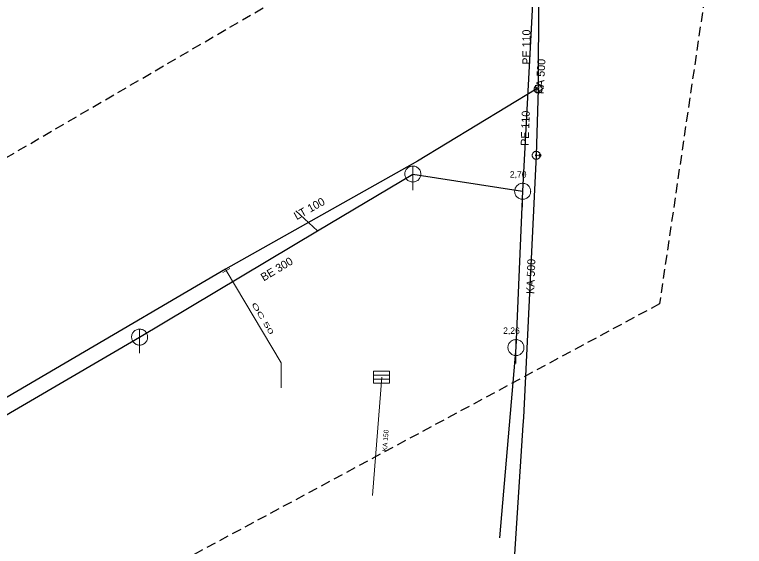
# Model space of a CAD drawing. Extents: x -689189 to -688666, y -973229 to -972850.
# Drawn here: x -688858.3 to -688767.2, y -972988.4 to -972922 of the extents above; entities that cross this region are included whole.
import ezdxf

# ---------------------------------------------------------------- set-up
doc = ezdxf.new("R2010")
doc.units = 0
doc.header["$LTSCALE"] = 0.4
doc.linetypes.add('MEDIUM_DASHED', pattern=[4.5, 3, -1.5])
doc.layers.add('1', color=7, linetype='Continuous')
for name, color, linetype, lineweight in [('11', 7, 'Continuous', 13), ('13', 7, 'Continuous', 13), ('14', 7, 'Continuous', 13), ('17', 7, 'Continuous', 25), ('22', 7, 'Continuous', 13), ('34', 7, 'Continuous', 13), ('47', 7, 'Continuous', 13), ('63', 7, 'MEDIUM_DASHED', 25), ('9', 7, 'Continuous', 13)]:
    doc.layers.add(name, color=color, linetype=linetype, lineweight=lineweight)

msp = doc.modelspace()

# ---------------------------------------------------------------- linework, layer by layer
at = {"layer": '11'}
for p, q in [((-688823.171, -972946.507), (-688820.467, -972949.003)), ((-688812.451, -972967.272), (-688813.601, -972982.025))]:
    msp.add_line(p, q, dxfattribs=at)
at = {"layer": '13'}
msp.add_lwpolyline([(-688831.857, -972953.962), (-688825.015, -972965.466), (-688825.015, -972968.601)], dxfattribs=at)
at = {"layer": '14', "lineweight": 25}
for p, q in [((-688793.27, -972913.607), (-688794.848, -972944.059)), ((-688808.566, -972941.901), (-688794.848, -972944.059)), ((-688794.848, -972944.059), (-688795.686, -972963.568)), ((-688795.686, -972963.568), (-688797.745, -972987.344))]:
    msp.add_line(p, q, dxfattribs=at)
at = {"layer": '14'}
for p, q in [((-688792.916, -972931.292), (-688793.177, -972931.292)), ((-688792.916, -972931.292), (-688792.912, -972931.053)), ((-688793.154, -972939.566), (-688792.683, -972939.579)), ((-688831.953, -972953.798), (-688831.857, -972953.962))]:
    msp.add_line(p, q, dxfattribs=at)
at = {"layer": '14', "lineweight": 25}
for points in [[(-688842.688, -972962.265), (-688820.467, -972949.003), (-688808.566, -972941.901)], [(-688951.66, -973026.25), (-688926.154, -973011.013), (-688911.58, -973002.657), (-688886.468, -972987.81), (-688879.879, -972983.977), (-688842.688, -972962.265)]]:
    msp.add_lwpolyline(points, dxfattribs=at)
at = {"layer": '17'}
for p, q in [((-688792.866, -972919.454), (-688792.912, -972931.053)), ((-688792.916, -972931.292), (-688793.154, -972939.566))]:
    msp.add_line(p, q, dxfattribs=at)
for points in [[(-688793.177, -972931.292), (-688807.995, -972940.316), (-688831.953, -972953.798), (-688872.059, -972977.27), (-688873.897, -972978.38), (-688874.46, -972978.719), (-688897.906, -972992.515), (-688964.11, -973031.504), (-688973.449, -973037.003), (-688975.824, -973038.94)], [(-688793.154, -972939.566), (-688794.76, -972972.294), (-688794.823, -972973.274), (-688797.579, -973015.741)]]:
    msp.add_lwpolyline(points, dxfattribs=at)
at = {"layer": '22'}
for p, q in [((-688808.566, -972943.901), (-688808.565, -972940.901)), ((-688794.848, -972946.059), (-688794.847, -972943.059)), ((-688842.688, -972964.265), (-688842.687, -972961.265)), ((-688795.686, -972965.568), (-688795.685, -972962.568)), ((-688813.462, -972967.015), (-688811.462, -972967.015)), ((-688813.462, -972967.515), (-688811.462, -972967.515))]:
    msp.add_line(p, q, dxfattribs=at)
for points in [[(-688807.566, -972941.901), (-688807.571, -972941.792), (-688807.589, -972941.684), (-688807.619, -972941.578), (-688807.659, -972941.477), (-688807.711, -972941.38), (-688807.773, -972941.29), (-688807.845, -972941.207), (-688807.925, -972941.133), (-688808.013, -972941.067), (-688808.107, -972941.012), (-688808.207, -972940.967), (-688808.312, -972940.934), (-688808.419, -972940.912), (-688808.528, -972940.902), (-688808.638, -972940.904), (-688808.746, -972940.918), (-688808.853, -972940.943), (-688808.956, -972940.98), (-688809.054, -972941.029), (-688809.146, -972941.087), (-688809.232, -972941.156), (-688809.309, -972941.233), (-688809.378, -972941.319), (-688809.437, -972941.411), (-688809.485, -972941.509), (-688809.522, -972941.612), (-688809.548, -972941.719), (-688809.562, -972941.827), (-688809.565, -972941.937), (-688809.555, -972942.046), (-688809.534, -972942.153), (-688809.5, -972942.257), (-688809.456, -972942.357), (-688809.401, -972942.452), (-688809.335, -972942.54), (-688809.261, -972942.62), (-688809.178, -972942.692), (-688809.088, -972942.754), (-688808.992, -972942.806), (-688808.89, -972942.847), (-688808.785, -972942.877), (-688808.677, -972942.895), (-688808.567, -972942.901), (-688808.458, -972942.895), (-688808.35, -972942.877), (-688808.245, -972942.848), (-688808.143, -972942.807), (-688808.046, -972942.755), (-688807.956, -972942.693), (-688807.873, -972942.622), (-688807.798, -972942.542), (-688807.733, -972942.454), (-688807.677, -972942.36), (-688807.633, -972942.26), (-688807.599, -972942.156), (-688807.577, -972942.048), (-688807.567, -972941.939)], [(-688793.848, -972944.059), (-688793.853, -972943.95), (-688793.871, -972943.842), (-688793.901, -972943.736), (-688793.941, -972943.635), (-688793.993, -972943.538), (-688794.055, -972943.448), (-688794.127, -972943.365), (-688794.207, -972943.291), (-688794.295, -972943.225), (-688794.389, -972943.17), (-688794.489, -972943.125), (-688794.594, -972943.092), (-688794.701, -972943.07), (-688794.81, -972943.06), (-688794.92, -972943.062), (-688795.028, -972943.076), (-688795.135, -972943.101), (-688795.238, -972943.138), (-688795.336, -972943.187), (-688795.428, -972943.245), (-688795.514, -972943.314), (-688795.591, -972943.391), (-688795.66, -972943.477), (-688795.719, -972943.569), (-688795.767, -972943.667), (-688795.804, -972943.77), (-688795.83, -972943.877), (-688795.844, -972943.985), (-688795.847, -972944.095), (-688795.837, -972944.204), (-688795.816, -972944.311), (-688795.782, -972944.415), (-688795.738, -972944.515), (-688795.683, -972944.61), (-688795.617, -972944.698), (-688795.543, -972944.778), (-688795.46, -972944.85), (-688795.37, -972944.912), (-688795.274, -972944.964), (-688795.172, -972945.005), (-688795.067, -972945.035), (-688794.959, -972945.053), (-688794.849, -972945.059), (-688794.74, -972945.053), (-688794.632, -972945.035), (-688794.527, -972945.006), (-688794.425, -972944.965), (-688794.328, -972944.913), (-688794.238, -972944.851), (-688794.155, -972944.78), (-688794.08, -972944.7), (-688794.015, -972944.612), (-688793.959, -972944.518), (-688793.915, -972944.418), (-688793.881, -972944.314), (-688793.859, -972944.206), (-688793.849, -972944.097)], [(-688841.688, -972962.265), (-688841.693, -972962.156), (-688841.711, -972962.048), (-688841.741, -972961.942), (-688841.781, -972961.841), (-688841.833, -972961.744), (-688841.895, -972961.654), (-688841.967, -972961.571), (-688842.047, -972961.497), (-688842.135, -972961.431), (-688842.229, -972961.376), (-688842.329, -972961.331), (-688842.434, -972961.298), (-688842.541, -972961.276), (-688842.65, -972961.266), (-688842.76, -972961.268), (-688842.868, -972961.282), (-688842.975, -972961.307), (-688843.078, -972961.344), (-688843.176, -972961.393), (-688843.268, -972961.451), (-688843.354, -972961.52), (-688843.431, -972961.597), (-688843.5, -972961.683), (-688843.559, -972961.775), (-688843.607, -972961.873), (-688843.644, -972961.976), (-688843.67, -972962.083), (-688843.684, -972962.191), (-688843.687, -972962.301), (-688843.677, -972962.41), (-688843.656, -972962.517), (-688843.622, -972962.621), (-688843.578, -972962.721), (-688843.523, -972962.816), (-688843.457, -972962.904), (-688843.383, -972962.984), (-688843.3, -972963.056), (-688843.21, -972963.118), (-688843.114, -972963.17), (-688843.012, -972963.211), (-688842.907, -972963.241), (-688842.799, -972963.259), (-688842.689, -972963.265), (-688842.58, -972963.259), (-688842.472, -972963.241), (-688842.367, -972963.212), (-688842.265, -972963.171), (-688842.168, -972963.119), (-688842.078, -972963.057), (-688841.995, -972962.986), (-688841.92, -972962.906), (-688841.855, -972962.818), (-688841.799, -972962.724), (-688841.755, -972962.624), (-688841.721, -972962.52), (-688841.699, -972962.412), (-688841.689, -972962.303)], [(-688794.686, -972963.568), (-688794.691, -972963.459), (-688794.709, -972963.351), (-688794.739, -972963.245), (-688794.779, -972963.144), (-688794.831, -972963.047), (-688794.893, -972962.957), (-688794.965, -972962.874), (-688795.045, -972962.8), (-688795.133, -972962.734), (-688795.227, -972962.679), (-688795.327, -972962.634), (-688795.432, -972962.601), (-688795.539, -972962.579), (-688795.648, -972962.569), (-688795.758, -972962.571), (-688795.866, -972962.585), (-688795.973, -972962.61), (-688796.076, -972962.647), (-688796.174, -972962.696), (-688796.266, -972962.754), (-688796.352, -972962.823), (-688796.429, -972962.9), (-688796.498, -972962.986), (-688796.557, -972963.078), (-688796.605, -972963.176), (-688796.642, -972963.279), (-688796.668, -972963.386), (-688796.682, -972963.494), (-688796.685, -972963.604), (-688796.675, -972963.713), (-688796.654, -972963.82), (-688796.62, -972963.924), (-688796.576, -972964.024), (-688796.521, -972964.119), (-688796.455, -972964.207), (-688796.381, -972964.287), (-688796.298, -972964.359), (-688796.208, -972964.421), (-688796.112, -972964.473), (-688796.01, -972964.514), (-688795.905, -972964.544), (-688795.797, -972964.562), (-688795.687, -972964.568), (-688795.578, -972964.562), (-688795.47, -972964.544), (-688795.365, -972964.515), (-688795.263, -972964.474), (-688795.166, -972964.422), (-688795.076, -972964.36), (-688794.993, -972964.289), (-688794.918, -972964.209), (-688794.853, -972964.121), (-688794.797, -972964.027), (-688794.753, -972963.927), (-688794.719, -972963.823), (-688794.697, -972963.715), (-688794.687, -972963.606)], [(-688813.462, -972966.515), (-688811.462, -972966.515), (-688811.462, -972968.015), (-688813.462, -972968.015)]]:
    msp.add_lwpolyline(points, close=True, dxfattribs=at)
at = {"layer": '34'}
for p, q in [((-688793.245, -972930.796), (-688793.109, -972931.787)), ((-688792.412, -972931.026), (-688793.411, -972931.078)), ((-688831.425, -972953.709), (-688832.289, -972954.213))]:
    msp.add_line(p, q, dxfattribs=at)
at = {"layer": '47'}
for points in [[(-688792.51, -972930.999), (-688792.543, -972930.958), (-688792.58, -972930.921), (-688792.621, -972930.889), (-688792.664, -972930.859), (-688792.711, -972930.835), (-688792.76, -972930.817), (-688792.81, -972930.804), (-688792.862, -972930.795), (-688792.914, -972930.792), (-688792.966, -972930.794), (-688793.019, -972930.802), (-688793.069, -972930.816), (-688793.118, -972930.834), (-688793.164, -972930.858), (-688793.208, -972930.886), (-688793.249, -972930.919), (-688793.286, -972930.956), (-688793.319, -972930.997), (-688793.348, -972931.04), (-688793.372, -972931.087), (-688793.39, -972931.136), (-688793.404, -972931.187), (-688793.413, -972931.239), (-688793.416, -972931.29), (-688793.413, -972931.342), (-688793.405, -972931.395), (-688793.392, -972931.445), (-688793.373, -972931.494), (-688793.349, -972931.54), (-688793.321, -972931.584), (-688793.288, -972931.625), (-688793.251, -972931.662), (-688793.211, -972931.696), (-688793.167, -972931.724), (-688793.12, -972931.748), (-688793.072, -972931.767), (-688793.021, -972931.781), (-688792.969, -972931.789), (-688792.917, -972931.792), (-688792.865, -972931.789), (-688792.812, -972931.781), (-688792.762, -972931.768), (-688792.713, -972931.749), (-688792.667, -972931.725), (-688792.623, -972931.697), (-688792.582, -972931.664), (-688792.545, -972931.627), (-688792.512, -972931.587), (-688792.483, -972931.543), (-688792.459, -972931.496), (-688792.44, -972931.448), (-688792.427, -972931.397), (-688792.419, -972931.346), (-688792.416, -972931.293), (-688792.418, -972931.241), (-688792.426, -972931.188), (-688792.44, -972931.139), (-688792.458, -972931.089), (-688792.482, -972931.043)], [(-688792.849, -972931.243), (-688792.854, -972931.236), (-688792.861, -972931.231), (-688792.867, -972931.226), (-688792.874, -972931.221), (-688792.882, -972931.217), (-688792.89, -972931.214), (-688792.898, -972931.211), (-688792.907, -972931.21), (-688792.915, -972931.21), (-688792.924, -972931.21), (-688792.933, -972931.211), (-688792.941, -972931.214), (-688792.949, -972931.217), (-688792.956, -972931.22), (-688792.964, -972931.225), (-688792.971, -972931.23), (-688792.976, -972931.237), (-688792.981, -972931.243), (-688792.986, -972931.25), (-688792.99, -972931.258), (-688792.993, -972931.266), (-688792.996, -972931.274), (-688792.997, -972931.283), (-688792.998, -972931.292), (-688792.997, -972931.3), (-688792.996, -972931.309), (-688792.993, -972931.317), (-688792.99, -972931.325), (-688792.987, -972931.332), (-688792.982, -972931.34), (-688792.977, -972931.347), (-688792.97, -972931.352), (-688792.964, -972931.357), (-688792.957, -972931.362), (-688792.949, -972931.366), (-688792.942, -972931.37), (-688792.933, -972931.372), (-688792.924, -972931.373), (-688792.915, -972931.374), (-688792.907, -972931.373), (-688792.898, -972931.372), (-688792.89, -972931.369), (-688792.882, -972931.366), (-688792.875, -972931.363), (-688792.867, -972931.358), (-688792.86, -972931.353), (-688792.855, -972931.346), (-688792.85, -972931.34), (-688792.845, -972931.333), (-688792.841, -972931.325), (-688792.837, -972931.318), (-688792.835, -972931.309), (-688792.834, -972931.3), (-688792.834, -972931.292), (-688792.834, -972931.283), (-688792.835, -972931.274), (-688792.838, -972931.266), (-688792.841, -972931.258), (-688792.844, -972931.251)], [(-688792.748, -972939.273), (-688792.781, -972939.232), (-688792.818, -972939.195), (-688792.859, -972939.163), (-688792.902, -972939.133), (-688792.949, -972939.109), (-688792.998, -972939.091), (-688793.048, -972939.078), (-688793.1, -972939.069), (-688793.152, -972939.066), (-688793.204, -972939.068), (-688793.257, -972939.076), (-688793.307, -972939.09), (-688793.356, -972939.108), (-688793.402, -972939.132), (-688793.446, -972939.16), (-688793.487, -972939.193), (-688793.524, -972939.23), (-688793.557, -972939.271), (-688793.586, -972939.314), (-688793.61, -972939.361), (-688793.628, -972939.41), (-688793.642, -972939.461), (-688793.651, -972939.513), (-688793.654, -972939.564), (-688793.651, -972939.616), (-688793.643, -972939.669), (-688793.63, -972939.719), (-688793.611, -972939.768), (-688793.587, -972939.814), (-688793.559, -972939.858), (-688793.526, -972939.899), (-688793.489, -972939.936), (-688793.449, -972939.97), (-688793.405, -972939.998), (-688793.358, -972940.022), (-688793.31, -972940.041), (-688793.259, -972940.055), (-688793.207, -972940.063), (-688793.155, -972940.066), (-688793.103, -972940.063), (-688793.05, -972940.055), (-688793, -972940.042), (-688792.951, -972940.023), (-688792.905, -972939.999), (-688792.861, -972939.971), (-688792.82, -972939.938), (-688792.783, -972939.901), (-688792.75, -972939.861), (-688792.721, -972939.817), (-688792.697, -972939.77), (-688792.678, -972939.722), (-688792.665, -972939.671), (-688792.657, -972939.62), (-688792.654, -972939.567), (-688792.656, -972939.515), (-688792.664, -972939.462), (-688792.678, -972939.413), (-688792.696, -972939.363), (-688792.72, -972939.317)], [(-688793.087, -972939.517), (-688793.092, -972939.51), (-688793.099, -972939.505), (-688793.105, -972939.5), (-688793.112, -972939.495), (-688793.12, -972939.491), (-688793.128, -972939.488), (-688793.136, -972939.485), (-688793.145, -972939.484), (-688793.153, -972939.484), (-688793.162, -972939.484), (-688793.171, -972939.485), (-688793.179, -972939.488), (-688793.187, -972939.491), (-688793.194, -972939.494), (-688793.202, -972939.499), (-688793.209, -972939.504), (-688793.214, -972939.511), (-688793.219, -972939.517), (-688793.224, -972939.524), (-688793.228, -972939.532), (-688793.231, -972939.54), (-688793.234, -972939.548), (-688793.235, -972939.557), (-688793.236, -972939.566), (-688793.235, -972939.574), (-688793.234, -972939.583), (-688793.231, -972939.591), (-688793.228, -972939.599), (-688793.225, -972939.606), (-688793.22, -972939.614), (-688793.215, -972939.621), (-688793.208, -972939.626), (-688793.202, -972939.631), (-688793.195, -972939.636), (-688793.187, -972939.64), (-688793.18, -972939.644), (-688793.171, -972939.646), (-688793.162, -972939.647), (-688793.153, -972939.648), (-688793.145, -972939.647), (-688793.136, -972939.646), (-688793.128, -972939.643), (-688793.12, -972939.64), (-688793.113, -972939.637), (-688793.105, -972939.632), (-688793.098, -972939.627), (-688793.093, -972939.62), (-688793.088, -972939.614), (-688793.083, -972939.607), (-688793.079, -972939.599), (-688793.075, -972939.592), (-688793.073, -972939.583), (-688793.072, -972939.574), (-688793.072, -972939.566), (-688793.072, -972939.557), (-688793.073, -972939.548), (-688793.076, -972939.54), (-688793.079, -972939.532), (-688793.082, -972939.525)]]:
    msp.add_lwpolyline(points, close=True, dxfattribs=at)
at = {"layer": '63'}
msp.add_lwpolyline([(-689164.065, -973177.51), (-689187.511, -973131.176), (-688767.155, -972886.107), (-688767.155, -972886.107), (-688777.761, -972958.121), (-688777.761, -972958.121), (-688989.335, -973072.002), (-688989.335, -973072.002)], close=True, dxfattribs=at)
at = {"layer": '9'}
for points in [[(-688792.809, -972939.579), (-688792.809, -972939.592), (-688792.806, -972939.605), (-688792.804, -972939.618), (-688792.799, -972939.63), (-688792.793, -972939.642), (-688792.786, -972939.653), (-688792.777, -972939.663), (-688792.767, -972939.673), (-688792.757, -972939.681), (-688792.747, -972939.688), (-688792.735, -972939.694), (-688792.723, -972939.699), (-688792.71, -972939.702), (-688792.696, -972939.704), (-688792.684, -972939.706), (-688792.671, -972939.705), (-688792.657, -972939.703), (-688792.645, -972939.7), (-688792.632, -972939.695), (-688792.62, -972939.689), (-688792.61, -972939.682), (-688792.6, -972939.674), (-688792.59, -972939.664), (-688792.581, -972939.654), (-688792.575, -972939.643), (-688792.569, -972939.631), (-688792.564, -972939.619), (-688792.561, -972939.606), (-688792.559, -972939.593), (-688792.556, -972939.58), (-688792.558, -972939.567), (-688792.559, -972939.554), (-688792.563, -972939.541), (-688792.568, -972939.529), (-688792.573, -972939.517), (-688792.581, -972939.506), (-688792.588, -972939.496), (-688792.598, -972939.486), (-688792.608, -972939.478), (-688792.62, -972939.471), (-688792.632, -972939.465), (-688792.644, -972939.46), (-688792.657, -972939.457), (-688792.669, -972939.455), (-688792.683, -972939.454), (-688792.696, -972939.454), (-688792.708, -972939.456), (-688792.722, -972939.459), (-688792.733, -972939.464), (-688792.745, -972939.47), (-688792.757, -972939.477), (-688792.767, -972939.485), (-688792.777, -972939.495), (-688792.784, -972939.505), (-688792.792, -972939.516), (-688792.798, -972939.528), (-688792.803, -972939.54), (-688792.806, -972939.553), (-688792.808, -972939.566)], [(-688792.789, -972939.579), (-688792.789, -972939.59), (-688792.788, -972939.601), (-688792.784, -972939.612), (-688792.781, -972939.622), (-688792.776, -972939.632), (-688792.77, -972939.641), (-688792.762, -972939.65), (-688792.755, -972939.658), (-688792.745, -972939.665), (-688792.737, -972939.671), (-688792.727, -972939.676), (-688792.717, -972939.68), (-688792.706, -972939.683), (-688792.695, -972939.686), (-688792.684, -972939.686), (-688792.673, -972939.686), (-688792.662, -972939.684), (-688792.651, -972939.681), (-688792.641, -972939.677), (-688792.63, -972939.672), (-688792.622, -972939.666), (-688792.613, -972939.659), (-688792.605, -972939.651), (-688792.598, -972939.642), (-688792.592, -972939.633), (-688792.587, -972939.623), (-688792.583, -972939.613), (-688792.58, -972939.602), (-688792.578, -972939.591), (-688792.576, -972939.58), (-688792.576, -972939.569), (-688792.578, -972939.558), (-688792.581, -972939.547), (-688792.586, -972939.537), (-688792.591, -972939.527), (-688792.597, -972939.518), (-688792.603, -972939.509), (-688792.612, -972939.501), (-688792.62, -972939.494), (-688792.63, -972939.488), (-688792.64, -972939.483), (-688792.649, -972939.479), (-688792.661, -972939.476), (-688792.671, -972939.474), (-688792.683, -972939.474), (-688792.694, -972939.473), (-688792.705, -972939.475), (-688792.716, -972939.478), (-688792.725, -972939.482), (-688792.735, -972939.487), (-688792.745, -972939.493), (-688792.754, -972939.5), (-688792.762, -972939.508), (-688792.769, -972939.517), (-688792.774, -972939.526), (-688792.779, -972939.536), (-688792.784, -972939.546), (-688792.787, -972939.557), (-688792.789, -972939.568)], [(-688792.77, -972939.579), (-688792.77, -972939.588), (-688792.769, -972939.597), (-688792.766, -972939.606), (-688792.762, -972939.614), (-688792.759, -972939.622), (-688792.754, -972939.63), (-688792.747, -972939.637), (-688792.742, -972939.643), (-688792.735, -972939.649), (-688792.727, -972939.654), (-688792.718, -972939.658), (-688792.711, -972939.661), (-688792.701, -972939.664), (-688792.693, -972939.665), (-688792.684, -972939.667), (-688792.674, -972939.666), (-688792.666, -972939.665), (-688792.657, -972939.662), (-688792.649, -972939.659), (-688792.641, -972939.655), (-688792.632, -972939.65), (-688792.625, -972939.644), (-688792.62, -972939.638), (-688792.614, -972939.631), (-688792.608, -972939.623), (-688792.605, -972939.615), (-688792.602, -972939.607), (-688792.598, -972939.598), (-688792.598, -972939.589), (-688792.595, -972939.58), (-688792.597, -972939.571), (-688792.598, -972939.562), (-688792.6, -972939.553), (-688792.603, -972939.545), (-688792.608, -972939.537), (-688792.613, -972939.529), (-688792.619, -972939.522), (-688792.625, -972939.516), (-688792.632, -972939.51), (-688792.64, -972939.505), (-688792.647, -972939.501), (-688792.656, -972939.498), (-688792.664, -972939.495), (-688792.674, -972939.494), (-688792.683, -972939.493), (-688792.691, -972939.493), (-688792.701, -972939.494), (-688792.71, -972939.497), (-688792.718, -972939.5), (-688792.725, -972939.504), (-688792.733, -972939.509), (-688792.74, -972939.515), (-688792.747, -972939.521), (-688792.752, -972939.528), (-688792.757, -972939.536), (-688792.762, -972939.544), (-688792.765, -972939.552), (-688792.767, -972939.561), (-688792.769, -972939.57)], [(-688792.75, -972939.579), (-688792.75, -972939.586), (-688792.749, -972939.593), (-688792.747, -972939.6), (-688792.745, -972939.606), (-688792.742, -972939.612), (-688792.738, -972939.618), (-688792.733, -972939.624), (-688792.728, -972939.629), (-688792.723, -972939.633), (-688792.717, -972939.637), (-688792.711, -972939.64), (-688792.705, -972939.643), (-688792.698, -972939.644), (-688792.691, -972939.647), (-688792.684, -972939.647), (-688792.676, -972939.647), (-688792.669, -972939.645), (-688792.663, -972939.644), (-688792.657, -972939.641), (-688792.649, -972939.638), (-688792.645, -972939.634), (-688792.639, -972939.63), (-688792.634, -972939.625), (-688792.63, -972939.619), (-688792.625, -972939.613), (-688792.622, -972939.607), (-688792.62, -972939.601), (-688792.618, -972939.594), (-688792.617, -972939.587), (-688792.615, -972939.58), (-688792.615, -972939.573), (-688792.617, -972939.566), (-688792.619, -972939.559), (-688792.622, -972939.553), (-688792.625, -972939.546), (-688792.629, -972939.541), (-688792.632, -972939.535), (-688792.637, -972939.53), (-688792.644, -972939.526), (-688792.649, -972939.522), (-688792.656, -972939.519), (-688792.662, -972939.516), (-688792.669, -972939.514), (-688792.676, -972939.513), (-688792.683, -972939.513), (-688792.69, -972939.513), (-688792.696, -972939.513), (-688792.703, -972939.515), (-688792.71, -972939.518), (-688792.716, -972939.521), (-688792.722, -972939.525), (-688792.728, -972939.529), (-688792.733, -972939.534), (-688792.737, -972939.54), (-688792.74, -972939.545), (-688792.744, -972939.552), (-688792.747, -972939.558), (-688792.747, -972939.565), (-688792.75, -972939.572)], [(-688792.73, -972939.579), (-688792.73, -972939.584), (-688792.73, -972939.589), (-688792.728, -972939.594), (-688792.727, -972939.598), (-688792.725, -972939.603), (-688792.722, -972939.607), (-688792.718, -972939.61), (-688792.715, -972939.614), (-688792.712, -972939.617), (-688792.708, -972939.62), (-688792.703, -972939.622), (-688792.698, -972939.624), (-688792.694, -972939.625), (-688792.689, -972939.627), (-688792.684, -972939.627), (-688792.679, -972939.627), (-688792.674, -972939.626), (-688792.669, -972939.625), (-688792.664, -972939.623), (-688792.659, -972939.621), (-688792.656, -972939.618), (-688792.652, -972939.615), (-688792.649, -972939.611), (-688792.646, -972939.608), (-688792.642, -972939.604), (-688792.641, -972939.599), (-688792.639, -972939.595), (-688792.637, -972939.59), (-688792.637, -972939.585), (-688792.636, -972939.58), (-688792.636, -972939.575), (-688792.637, -972939.57), (-688792.637, -972939.565), (-688792.64, -972939.561), (-688792.642, -972939.556), (-688792.645, -972939.552), (-688792.647, -972939.548), (-688792.651, -972939.545), (-688792.654, -972939.542), (-688792.659, -972939.539), (-688792.664, -972939.537), (-688792.668, -972939.535), (-688792.673, -972939.534), (-688792.678, -972939.533), (-688792.683, -972939.533), (-688792.688, -972939.533), (-688792.693, -972939.534), (-688792.698, -972939.534), (-688792.701, -972939.536), (-688792.706, -972939.538), (-688792.711, -972939.541), (-688792.713, -972939.544), (-688792.718, -972939.547), (-688792.72, -972939.551), (-688792.723, -972939.555), (-688792.725, -972939.56), (-688792.728, -972939.564), (-688792.728, -972939.569), (-688792.73, -972939.574)], [(-688792.71, -972939.579), (-688792.71, -972939.582), (-688792.711, -972939.585), (-688792.71, -972939.587), (-688792.708, -972939.59), (-688792.708, -972939.593), (-688792.706, -972939.595), (-688792.703, -972939.597), (-688792.701, -972939.599), (-688792.7, -972939.601), (-688792.698, -972939.603), (-688792.695, -972939.605), (-688792.691, -972939.606), (-688792.69, -972939.606), (-688792.686, -972939.607), (-688792.684, -972939.607), (-688792.681, -972939.607), (-688792.678, -972939.607), (-688792.674, -972939.606), (-688792.673, -972939.605), (-688792.669, -972939.604), (-688792.668, -972939.602), (-688792.664, -972939.6), (-688792.663, -972939.598), (-688792.662, -972939.596), (-688792.659, -972939.594), (-688792.659, -972939.591), (-688792.657, -972939.588), (-688792.657, -972939.586), (-688792.656, -972939.583), (-688792.654, -972939.58), (-688792.656, -972939.577), (-688792.656, -972939.574), (-688792.657, -972939.571), (-688792.657, -972939.569), (-688792.659, -972939.566), (-688792.661, -972939.564), (-688792.662, -972939.561), (-688792.664, -972939.559), (-688792.667, -972939.558), (-688792.669, -972939.556), (-688792.671, -972939.555), (-688792.674, -972939.554), (-688792.676, -972939.553), (-688792.679, -972939.553), (-688792.683, -972939.552), (-688792.686, -972939.553), (-688792.689, -972939.552), (-688792.691, -972939.554), (-688792.694, -972939.554), (-688792.696, -972939.555), (-688792.698, -972939.557), (-688792.701, -972939.558), (-688792.703, -972939.56), (-688792.705, -972939.563), (-688792.706, -972939.565), (-688792.708, -972939.568), (-688792.708, -972939.57), (-688792.71, -972939.573), (-688792.71, -972939.576)], [(-688792.691, -972939.579), (-688792.691, -972939.581), (-688792.691, -972939.581), (-688792.69, -972939.581), (-688792.69, -972939.583), (-688792.691, -972939.584), (-688792.689, -972939.584), (-688792.689, -972939.584), (-688792.689, -972939.586), (-688792.689, -972939.586), (-688792.688, -972939.587), (-688792.686, -972939.587), (-688792.686, -972939.587), (-688792.686, -972939.588), (-688792.684, -972939.588), (-688792.684, -972939.588), (-688792.683, -972939.588), (-688792.681, -972939.588), (-688792.681, -972939.587), (-688792.681, -972939.587), (-688792.679, -972939.587), (-688792.679, -972939.586), (-688792.679, -972939.586), (-688792.678, -972939.585), (-688792.678, -972939.585), (-688792.676, -972939.584), (-688792.676, -972939.583), (-688792.674, -972939.582), (-688792.674, -972939.582), (-688792.674, -972939.581), (-688792.674, -972939.58), (-688792.674, -972939.579), (-688792.674, -972939.578), (-688792.674, -972939.578), (-688792.676, -972939.577), (-688792.676, -972939.576), (-688792.676, -972939.575), (-688792.676, -972939.575), (-688792.678, -972939.574), (-688792.678, -972939.574), (-688792.679, -972939.573), (-688792.679, -972939.573), (-688792.681, -972939.572), (-688792.681, -972939.572), (-688792.681, -972939.572), (-688792.683, -972939.572), (-688792.684, -972939.572), (-688792.684, -972939.572), (-688792.684, -972939.572), (-688792.686, -972939.573), (-688792.686, -972939.572), (-688792.688, -972939.574), (-688792.688, -972939.574), (-688792.689, -972939.574), (-688792.689, -972939.574), (-688792.69, -972939.576), (-688792.69, -972939.577), (-688792.69, -972939.578), (-688792.691, -972939.578), (-688792.691, -972939.579)]]:
    msp.add_lwpolyline(points, close=True, dxfattribs=at)

# ---------------------------------------------------------------- texts
at = {"layer": '1'}
for s, height, rotation, p in [('PE 110', 1, 90, (-688793.885, -972928.249)), ('KA 500', 1, 87, (-688792.23, -972931.931)), ('PE 110', 1, 88, (-688794.106, -972938.399)), ('LT 100', 1, 29, (-688823.072, -972947.669)), ('BE 300', 1, 31, (-688827.185, -972955.324)), ('KA 500', 1, 88, (-688793.412, -972956.896)), ('KA 150', 0.6, 86, (-688811.778, -972976.55))]:
    msp.add_text(s, height=height, rotation=rotation, dxfattribs=at).set_placement(p)
for s, p in [('2,70', (-688796.448, -972942.348)), ('2,26', (-688797.286, -972961.857))]:
    msp.add_text(s, height=0.8, dxfattribs=at).set_placement(p)
at = {"layer": '1', "width": 1.95}
msp.add_text('OC 50 ', height=0.6, rotation=301, dxfattribs=at).set_placement((-688828.737, -972958.148))

doc.saveas('drawing.dxf')
